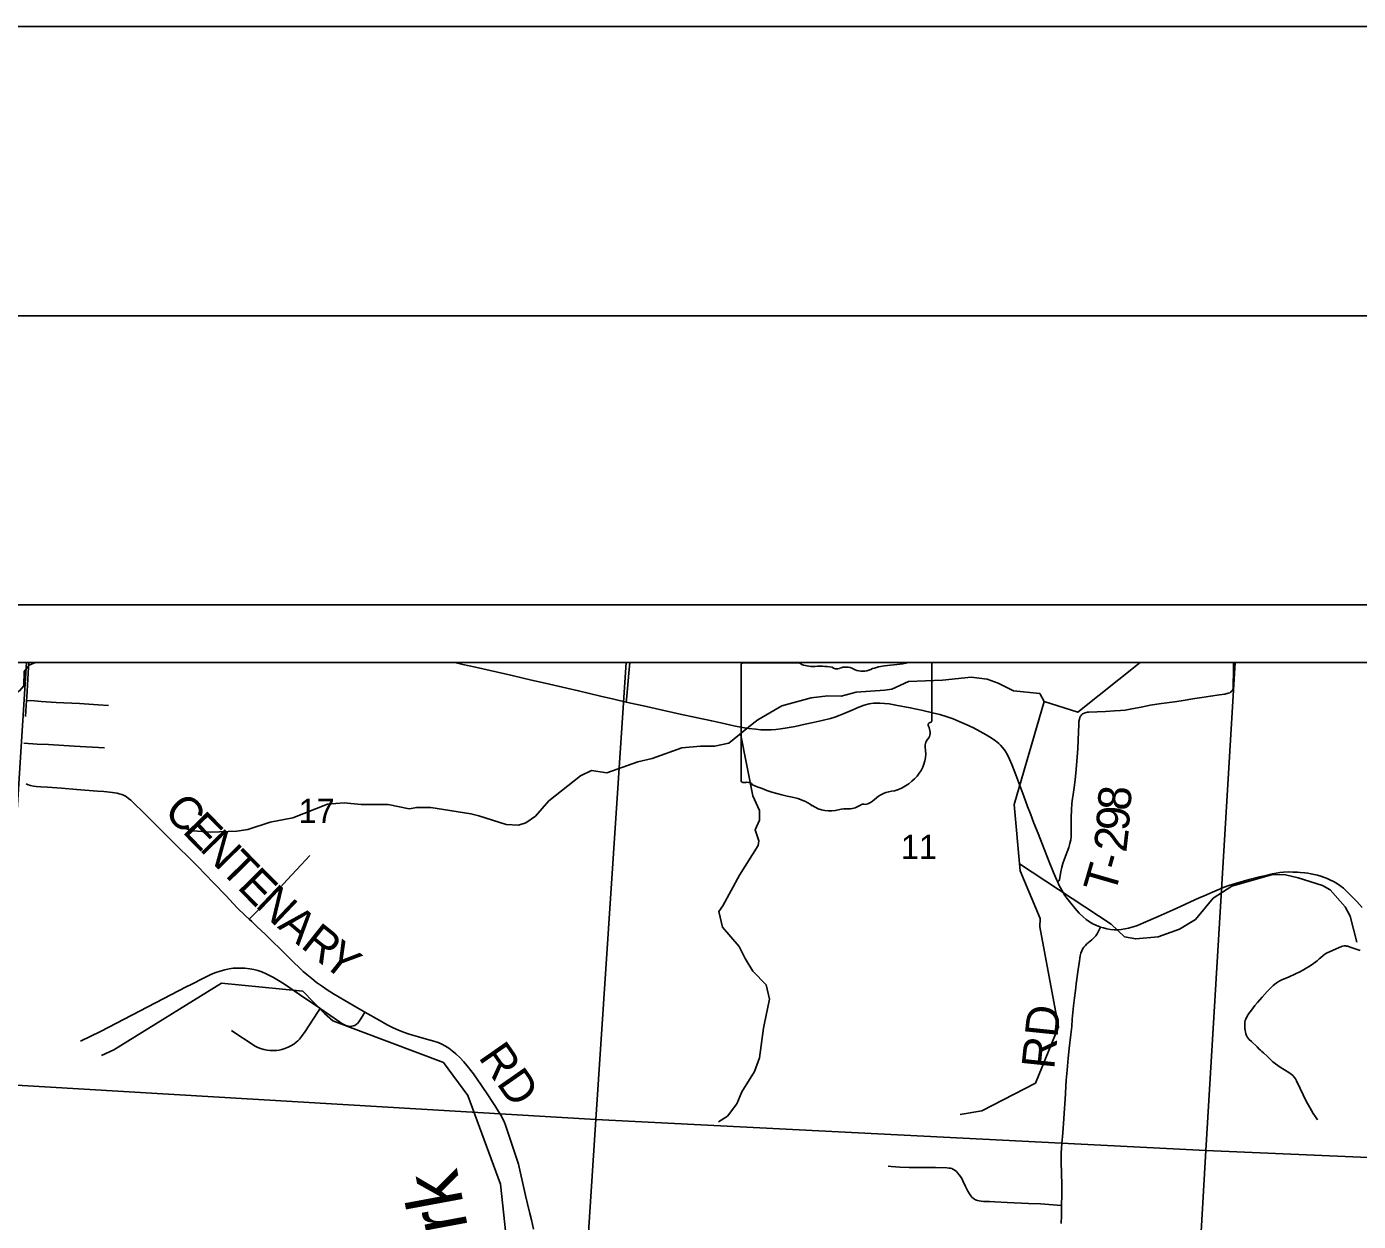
# Model space of a CAD drawing. Extents: x 0 to 34, y 0 to 22.
# Drawn here: x 24.586 to 26.889, y 19.934 to 22 of the extents above; entities that cross this region are included whole.
import ezdxf

# ---------------------------------------------------------------- set-up
doc = ezdxf.new("R2010")
doc.units = 0
for name, color, linetype in [('Default', 7, 'Continuous'), ('GM_X_County_Road', 7, 'Continuous'), ('GM_X_County_Road_Text', 7, 'Continuous'), ('GM_X_Minor_River', 7, 'Continuous'), ('GM_X_Minor_River_Text', 7, 'Continuous'), ('GM_X_Section', 7, 'Continuous'), ('GM_X_Section_Text', 7, 'Continuous'), ('GM_X_State_Location', 7, 'Continuous'), ('GM_X_State_Route', 7, 'Continuous'), ('GM_X_Township_Road', 7, 'Continuous'), ('GM_X_Township_Road_Text', 7, 'Continuous'), ('SH_Border', 7, 'Continuous'), ('SH_Cut_Line', 7, 'Continuous'), ('SH_Data', 7, 'Continuous'), ('SH_Text', 7, 'Continuous')]:
    doc.layers.add(name, color=color, linetype=linetype)

msp = doc.modelspace()

# ---------------------------------------------------------------- linework, layer by layer
at = {"layer": 'Default'}
for p, q in [((25.8216, 20.8963), (25.8216, 20.6962)), ((25.9214, 20.8998), (25.8248, 20.8998))]:
    msp.add_line(p, q, dxfattribs=at)
for points in [[(27.7198, 20.9), (23.5167, 20.9), (23.5167, 16.1239), (23.5888, 16.1195), (25.0535, 16.0331), (25.3458, 16.0191), (26.0811, 15.9921), (26.3691, 15.9829), (26.8773, 15.953), (26.8866, 15.9536), (26.8953, 15.9537)], [(26.1511, 20.8001), (26.1511, 20.8001), (26.1512, 20.8), (26.1512, 20.9), (26.1115, 20.9)]]:
    msp.add_lwpolyline(points, dxfattribs=at)
for points in [[(25.6226, 20.9), (24.5856, 20.9), (24.5388, 20.1708), (25.5703, 20.1097)], [(26.6756, 20.9), (25.6226, 20.9), (25.5703, 20.1097), (26.6253, 20.056)], [(27.7187, 20.9), (26.6756, 20.9), (26.6253, 20.056), (27.6689, 20.0112)]]:
    msp.add_lwpolyline(points, close=True, dxfattribs=at)
for centre, major_axis, start_param, end_param in [((25.8254, 20.8968), (0.00382, 0), 1.727492, 3.291633), ((25.9443, 20.923), (0.037, 0), 4.042888, 4.731792), ((25.9566, 20.7874), (0.133, 0), 1.404758, 1.657859), ((25.9868, 20.8978), (0.0107, 0), 3.836095, 5.185415), ((26.0025, 20.8747), (0.0222, 0), 0.950623, 2.079405), ((26.0783, 20.8386), (0.0703, 0), 1.699012, 2.107814), ((26.0338, 21.1726), (0.3495, 0), 4.814394, 4.936803), ((26.0312, 20.9064), (0.0267, 0), 4.08156, 5.145723), ((26.1473, 20.7996), (0.00393, 0), 5.05454, 6.418171), ((26.1503, 20.7924), (0.00568, 0), 1.883978, 3.671073), ((26.1142, 20.7791), (0.0341, 0), 5.934695, 6.695948), ((26.0533, 20.7429), (0.0874, 0), 5.101753, 6.440018), ((26.1643, 20.7562), (0.0248, 0), 2.387724, 3.262537), ((25.8254, 20.6958), (0.00385, 0), 2.993084, 4.5083), ((25.826, 20.7162), (0.0294, 0), 4.665946, 4.897461), ((25.832, 20.6847), (0.0106, 0), 0.519207, 1.627899), ((25.9658, 20.8645), (0.2524, 0), 4.195997, 4.488961), ((25.8906, 20.6063), (0.079, 0), 0.823519, 1.323587), ((26.0295, 20.6768), (0.0282, 0), 4.937069, 5.64225), ((26.0902, 20.64), (0.0479, 0), 1.647645, 2.488434), ((25.976, 20.6837), (0.0501, 0), 4.026481, 4.996735), ((26.0049, 20.6145), (0.0412, 0), 1.495662, 1.94098), ((26.0086, 20.6687), (0.0267, 0), 4.691044, 5.507374), ((26.0327, 20.6493), (0.00752, 0), 1.147584, 2.315152)]:
    msp.add_ellipse(centre, major_axis=major_axis, ratio=0.8, start_param=start_param, end_param=end_param, dxfattribs=at)
at = {"layer": 'GM_X_County_Road'}
for points in [[(24.5838, 20.8068), (24.5857, 20.8348), (24.586, 20.8406), (24.5871, 20.8611), (24.5885, 20.8822), (24.5897, 20.8995), (24.5897, 20.9)], [(25.4623, 19.9205), (25.4588, 19.9363), (25.4562, 19.9472), (25.4522, 19.9641), (25.4487, 19.9786), (25.4464, 19.9889), (25.444, 19.9992), (25.4398, 20.0173), (25.4361, 20.0324), (25.4335, 20.0414), (25.4284, 20.0567), (25.4217, 20.0761), (25.4143, 20.0986), (25.4114, 20.1067), (25.4088, 20.1118), (25.4068, 20.1156), (25.402, 20.1237), (25.3953, 20.1342), (25.3894, 20.1429), (25.3842, 20.1507), (25.3721, 20.1687), (25.3583, 20.1886), (25.3539, 20.1947), (25.3478, 20.2025), (25.3413, 20.2101), (25.3352, 20.2164), (25.3281, 20.2233), (25.3219, 20.2287), (25.3159, 20.2332), (25.3101, 20.2369), (25.304, 20.2401), (25.2976, 20.2428), (25.2899, 20.2454), (25.2774, 20.2491), (25.2636, 20.2529), (25.2475, 20.2575), (25.2375, 20.2608), (25.2289, 20.2642), (25.2198, 20.2682), (25.2094, 20.2736), (25.1953, 20.2815), (25.1708, 20.2956), (25.1679, 20.2973), (25.1565, 20.3037), (25.1362, 20.3157), (25.1165, 20.3275), (25.1054, 20.3344), (25.0972, 20.3399), (25.0871, 20.3471), (25.0788, 20.3535), (25.0703, 20.3606), (25.0642, 20.3659), (25.0592, 20.3705), (25.0453, 20.3838), (25.0344, 20.3948), (25.0278, 20.4014), (25.0074, 20.4214), (24.998, 20.4305), (24.9844, 20.4433), (24.9749, 20.4521), (24.9703, 20.4562), (24.9634, 20.4625), (24.9499, 20.4762), (24.93, 20.4971), (24.9093, 20.5189), (24.8941, 20.5345), (24.8828, 20.5461), (24.8697, 20.5593), (24.845, 20.5838), (24.834, 20.5948), (24.8171, 20.6112), (24.8078, 20.6204), (24.7913, 20.6372), (24.7839, 20.6447), (24.7754, 20.653), (24.7659, 20.6619), (24.7621, 20.6653), (24.7581, 20.6683), (24.7558, 20.6695), (24.7532, 20.6707), (24.7506, 20.6718), (24.746, 20.6733), (24.7421, 20.6742), (24.7341, 20.6755), (24.7192, 20.677), (24.708, 20.678), (24.6721, 20.6807), (24.6461, 20.6827), (24.6219, 20.6846), (24.6101, 20.6853), (24.6021, 20.686), (24.5978, 20.6865), (24.5924, 20.6875), (24.5883, 20.6887), (24.5862, 20.6897), (24.5846, 20.6906)]]:
    msp.add_lwpolyline(points, dxfattribs=at)
at = {"layer": 'GM_X_Minor_River'}
for points in [[(24.6012, 20.9), (24.5899, 20.8956), (24.5812, 20.8846), (24.5808, 20.8599), (24.5732, 20.8511), (24.5626, 20.845), (24.5535, 20.831), (24.5372, 20.8089), (24.5118, 20.7921), (24.486, 20.7666), (24.4792, 20.7628), (24.4651, 20.7282), (24.4211, 20.6669), (24.3878, 20.6262), (24.3703, 20.595), (24.3574, 20.581), (24.3517, 20.5745), (24.3286, 20.5539), (24.3187, 20.5383)], [(26.5115, 20.9), (26.4036, 20.8143), (26.3457, 20.8331), (26.2934, 20.6546), (26.304, 20.5397), (26.3388, 20.4577), (26.3379, 20.4433), (26.3705, 20.2701), (26.3304, 20.1726), (26.2377, 20.1247), (26.2002, 20.1187)], [(26.3456, 20.8331), (26.3378, 20.8465), (26.2927, 20.851), (26.2661, 20.8647), (26.2468, 20.8715), (26.2191, 20.8749), (26.1695, 20.8699), (26.1111, 20.8676), (26.0819, 20.8539), (26.0698, 20.8527), (26.0201, 20.8492), (25.9947, 20.842), (25.9712, 20.8427), (25.9424, 20.8389), (25.892, 20.8251), (25.8503, 20.8011), (25.8431, 20.7962), (25.8002, 20.7608), (25.7756, 20.7554), (25.7513, 20.7554), (25.7191, 20.7527), (25.6675, 20.734), (25.6425, 20.7283), (25.5894, 20.7092), (25.5625, 20.7134), (25.5436, 20.7043), (25.4886, 20.6608), (25.4655, 20.6346), (25.4488, 20.6228), (25.4366, 20.619), (25.415, 20.6201), (25.3677, 20.6352), (25.354, 20.6387), (25.2846, 20.6496), (25.2604, 20.6496), (25.2471, 20.6473), (25.2107, 20.6545), (25.1641, 20.6548), (25.1349, 20.6578), (25.1061, 20.6551), (25.0462, 20.6315), (25.0068, 20.6242), (24.9681, 20.6116), (24.9495, 20.6086), (24.9044, 20.607), (24.8737, 20.6093), (24.8574, 20.6138)], [(25.8205, 20.7775), (25.8415, 20.6696), (25.8533, 20.6441), (25.8529, 20.6274), (25.8457, 20.6107), (25.8521, 20.5917), (25.851, 20.584), (25.8187, 20.5327), (25.7899, 20.4794), (25.7831, 20.4695), (25.7891, 20.4426), (25.8179, 20.4091), (25.8281, 20.3882), (25.8418, 20.3662), (25.8645, 20.343), (25.8706, 20.3179), (25.8611, 20.2734), (25.8603, 20.2681), (25.8531, 20.2168), (25.8444, 20.1928), (25.8224, 20.1575), (25.814, 20.1369), (25.7977, 20.1156), (25.7822, 20.1061)], [(26.3029, 20.5519), (26.4612, 20.4475), (26.4846, 20.4257), (26.504, 20.4221), (26.5426, 20.4256), (26.5793, 20.4393), (26.6075, 20.456), (26.6378, 20.4928), (26.6699, 20.5133), (26.7402, 20.5335), (26.7626, 20.533), (26.785, 20.5276), (26.8269, 20.5147), (26.8402, 20.5069), (26.8663, 20.4779), (26.8745, 20.4616), (26.886, 20.4165)], [(25.6073, 18.8574), (25.5886, 18.9702), (25.6029, 19.0352), (25.6012, 19.1623), (25.5582, 19.2276), (25.4917, 19.2911), (25.4923, 19.3594), (25.4708, 19.4097), (25.4737, 19.5938), (25.4713, 19.6579), (25.427, 19.7941), (25.4053, 19.9981), (25.349, 20.1513), (25.3065, 20.2086), (25.115, 20.2805), (25.1008, 20.2933), (25.0631, 20.3317), (24.9228, 20.3456), (24.7364, 20.2301), (24.7153, 20.2204)]]:
    msp.add_lwpolyline(points, dxfattribs=at)
at = {"layer": 'GM_X_Section'}
for points in [[(24.5388, 20.1708), (25.5703, 20.1097), (25.5433, 19.6923), (25.5164, 19.2759), (25.5041, 19.0909), (25.5038, 19.0874), (24.9075, 19.1174), (24.4668, 19.1382), (24.4804, 19.3317), (24.5096, 19.7459)], [(25.5703, 20.1097), (26.6253, 20.056), (26.6008, 19.6356), (25.5433, 19.6923)], [(27.6689, 20.0112), (27.6061, 18.9865), (26.5652, 19.0298), (26.5757, 19.2125), (26.6008, 19.6356), (26.6253, 20.056)]]:
    msp.add_lwpolyline(points, close=True, dxfattribs=at)
at = {"layer": 'GM_X_State_Route'}
for points in [[(25.3264, 20.9), (25.34, 20.8969), (25.3619, 20.8923), (25.4254, 20.8778), (25.4586, 20.8699), (25.4823, 20.8646), (25.5198, 20.8561), (25.5404, 20.8513), (25.5784, 20.842), (25.6014, 20.8368), (25.6228, 20.8318)], [(25.6228, 20.8318), (25.6578, 20.8239), (25.6729, 20.8206), (25.716, 20.8111), (25.7433, 20.8054), (25.7705, 20.7993), (25.7863, 20.7959), (25.8088, 20.791), (25.824, 20.788), (25.8345, 20.7863), (25.8469, 20.7847), (25.8556, 20.784), (25.8643, 20.7837), (25.8731, 20.7838), (25.8812, 20.7844), (25.8899, 20.7853), (25.9009, 20.7871), (25.915, 20.7898), (25.932, 20.7936), (25.946, 20.7966), (25.9617, 20.8001), (25.9757, 20.8035), (25.9834, 20.8058), (25.9911, 20.8085), (25.9998, 20.8119), (26.0146, 20.8184), (26.0249, 20.8228), (26.0341, 20.8262), (26.043, 20.8285), (26.0503, 20.8297), (26.054, 20.83), (26.0579, 20.8301), (26.0613, 20.8301), (26.0693, 20.8295), (26.0773, 20.8285), (26.0889, 20.8266), (26.1139, 20.8219), (26.1358, 20.8174), (26.1521, 20.8135), (26.1653, 20.8101), (26.1778, 20.8063), (26.1883, 20.8026), (26.1986, 20.7985), (26.2105, 20.7933), (26.2234, 20.7871), (26.2349, 20.7811), (26.2452, 20.7754), (26.2541, 20.7698), (26.2612, 20.7649), (26.2669, 20.7602), (26.27, 20.7572), (26.2737, 20.7532), (26.2759, 20.7505), (26.278, 20.7473), (26.2821, 20.7404), (26.2856, 20.7332), (26.2893, 20.724), (26.2963, 20.7061), (26.3053, 20.6829), (26.3106, 20.669), (26.3169, 20.6515), (26.3216, 20.6386), (26.3279, 20.6224), (26.335, 20.6046), (26.3421, 20.5867), (26.3542, 20.5554), (26.3615, 20.5369), (26.3668, 20.5249), (26.3684, 20.5215), (26.3717, 20.5148), (26.3761, 20.5065), (26.3815, 20.4974), (26.3846, 20.4927), (26.3915, 20.4838), (26.3991, 20.4747), (26.4063, 20.4669), (26.4129, 20.4603), (26.4182, 20.4558), (26.4239, 20.4519), (26.4299, 20.4485), (26.4361, 20.4456), (26.4396, 20.4441), (26.4432, 20.4428), (26.4479, 20.4412), (26.454, 20.4397), (26.4602, 20.4387), (26.4665, 20.4382), (26.4721, 20.4382), (26.4784, 20.4386), (26.4852, 20.4395), (26.4914, 20.4408), (26.4992, 20.443), (26.5069, 20.4456), (26.5173, 20.4498), (26.5424, 20.4608), (26.5684, 20.4727), (26.5887, 20.482), (26.5983, 20.4864), (26.6124, 20.4926), (26.622, 20.4967), (26.6314, 20.5007), (26.6365, 20.5031), (26.6449, 20.5067), (26.6514, 20.5093), (26.6568, 20.5115), (26.665, 20.5144), (26.6762, 20.5179), (26.7001, 20.5247), (26.7181, 20.5294), (26.7296, 20.5321), (26.7405, 20.5345), (26.7533, 20.5368), (26.7596, 20.5376), (26.768, 20.538), (26.7754, 20.5379), (26.7834, 20.5377), (26.7885, 20.5373), (26.7962, 20.5366), (26.8014, 20.5358), (26.8068, 20.5349), (26.8122, 20.5338), (26.8182, 20.5323), (26.8241, 20.5306), (26.8285, 20.5291), (26.8321, 20.5277), (26.8352, 20.5265), (26.8398, 20.5246), (26.8458, 20.5217), (26.8511, 20.5185), (26.8567, 20.5147), (26.863, 20.5097), (26.8691, 20.5045), (26.8744, 20.4993), (26.8863, 20.4867), (26.8956, 20.4767)]]:
    msp.add_lwpolyline(points, dxfattribs=at)
at = {"layer": 'GM_X_Township_Road'}
for points in [[(25.6228, 20.8318), (25.6233, 20.8367), (25.6239, 20.8422), (25.6274, 20.8818), (25.6291, 20.9)], [(26.4057, 20.7983), (26.4064, 20.802), (26.4073, 20.805), (26.4084, 20.8073), (26.4093, 20.8088), (26.4103, 20.8099), (26.4118, 20.8113), (26.4133, 20.8123), (26.4163, 20.8135), (26.4181, 20.814), (26.4204, 20.8144), (26.4226, 20.8146), (26.437, 20.8152), (26.4518, 20.8158), (26.4673, 20.8164), (26.4777, 20.8171), (26.4857, 20.818), (26.4943, 20.8194), (26.5162, 20.8237), (26.529, 20.8262), (26.5487, 20.8293), (26.5708, 20.8322), (26.5825, 20.834), (26.6063, 20.8382), (26.618, 20.8399), (26.6334, 20.842), (26.6488, 20.8441), (26.6579, 20.8456), (26.6638, 20.8472), (26.6664, 20.8481), (26.668, 20.8491), (26.67, 20.8509), (26.671, 20.8523), (26.6717, 20.8537), (26.6721, 20.8554), (26.6722, 20.8571), (26.6726, 20.8632), (26.6727, 20.8824), (26.6732, 20.8972), (26.6733, 20.9)], [(24.5857, 20.8348), (24.599, 20.8337), (24.6107, 20.8328), (24.6367, 20.8312), (24.677, 20.8291), (24.7094, 20.8271), (24.7272, 20.8261)], [(26.3946, 20.6658), (26.3948, 20.6677), (26.3971, 20.6843), (26.3989, 20.6972), (26.4008, 20.7151), (26.4027, 20.7368), (26.4036, 20.7516), (26.4048, 20.7802), (26.4052, 20.7926), (26.4057, 20.7983)], [(24.5806, 20.7609), (24.6039, 20.7593), (24.6237, 20.7583), (24.6678, 20.7556), (24.7203, 20.7527)], [(26.3684, 20.5215), (26.3706, 20.5224), (26.3718, 20.5242), (26.3728, 20.5286), (26.3745, 20.5383), (26.3762, 20.5462), (26.378, 20.5528), (26.3805, 20.5605), (26.3879, 20.5803), (26.3901, 20.5873), (26.3915, 20.5933), (26.3921, 20.5995), (26.3923, 20.6075), (26.3923, 20.6324), (26.3927, 20.6454), (26.3935, 20.656), (26.3946, 20.6658)], [(24.9703, 20.4562), (24.9744, 20.4603), (24.9906, 20.4765), (25.0062, 20.4925), (25.0245, 20.5118), (25.0364, 20.5244), (25.0604, 20.5503), (25.0756, 20.5664)], [(26.3751, 19.9302), (26.3754, 19.9438), (26.3756, 19.9613), (26.3758, 19.9798), (26.3758, 19.9972), (26.3755, 20.0165), (26.375, 20.0364), (26.3751, 20.0519), (26.3754, 20.0606), (26.3758, 20.0681), (26.3775, 20.0866), (26.3798, 20.1114), (26.3809, 20.1287), (26.3816, 20.1442), (26.3833, 20.1779), (26.385, 20.1953), (26.3872, 20.216), (26.389, 20.2327), (26.3917, 20.2568), (26.3931, 20.271), (26.3942, 20.2834), (26.3964, 20.3062), (26.398, 20.3204), (26.3995, 20.3328), (26.401, 20.3445), (26.4045, 20.3691), (26.4058, 20.3802), (26.408, 20.3931), (26.409, 20.3974), (26.4105, 20.4015), (26.4125, 20.4055), (26.4142, 20.4081), (26.4167, 20.411), (26.4194, 20.4136), (26.4281, 20.4206), (26.4321, 20.4244), (26.4348, 20.4277), (26.437, 20.4311), (26.4392, 20.4354), (26.4432, 20.4428)], [(26.8182, 20.1091), (26.8145, 20.1146), (26.8108, 20.1204), (26.8047, 20.1309), (26.7988, 20.1417), (26.7932, 20.1523), (26.788, 20.1634), (26.782, 20.177), (26.7802, 20.1803), (26.7784, 20.1828), (26.7754, 20.186), (26.7726, 20.1884), (26.7686, 20.1912), (26.7538, 20.2005), (26.7494, 20.2035), (26.7456, 20.2061), (26.7412, 20.2096), (26.7367, 20.2137), (26.7315, 20.2187), (26.7248, 20.2251), (26.722, 20.2276), (26.7197, 20.2297), (26.7175, 20.2318), (26.714, 20.2353), (26.704, 20.2446), (26.7, 20.2485), (26.6972, 20.2519), (26.6959, 20.254), (26.695, 20.2561), (26.6942, 20.2583), (26.6935, 20.2618), (26.6932, 20.2641), (26.6928, 20.2676), (26.6926, 20.2714), (26.6925, 20.2749), (26.6928, 20.2782), (26.6934, 20.2813), (26.6942, 20.2837), (26.6966, 20.2886), (26.6995, 20.2932), (26.7038, 20.2991), (26.71, 20.3068), (26.7142, 20.312), (26.7224, 20.3213), (26.7311, 20.331), (26.7375, 20.3378), (26.7416, 20.3416), (26.747, 20.3458), (26.7522, 20.3491), (26.7578, 20.3519), (26.768, 20.3563), (26.78, 20.3616), (26.7878, 20.3653), (26.7938, 20.3686), (26.7989, 20.3714), (26.8029, 20.374), (26.809, 20.3782), (26.8174, 20.3845), (26.8214, 20.3876), (26.8237, 20.3895), (26.8278, 20.3933), (26.831, 20.3958), (26.8339, 20.3975), (26.8456, 20.4028), (26.8546, 20.4069), (26.8596, 20.409), (26.8619, 20.4097), (26.8643, 20.41), (26.8664, 20.4101), (26.8684, 20.4098), (26.8709, 20.4094), (26.8745, 20.4082), (26.8815, 20.4056), (26.8866, 20.4037), (26.8919, 20.4023)], [(24.679, 20.2452), (24.7132, 20.2621), (24.8629, 20.3397), (24.8689, 20.3428), (24.8927, 20.3548), (24.9056, 20.361), (24.913, 20.3641), (24.9205, 20.3667), (24.9283, 20.3688), (24.9361, 20.3704), (24.9428, 20.3714), (24.9483, 20.3718), (24.9517, 20.3719), (24.9551, 20.3719), (24.9631, 20.3714), (24.9717, 20.3704), (24.9789, 20.3691), (24.9854, 20.3674), (24.9924, 20.365), (24.9999, 20.362), (25.006, 20.3591), (25.0125, 20.3555), (25.0215, 20.3501), (25.0314, 20.3437), (25.0576, 20.3259), (25.0926, 20.3023), (25.0933, 20.3018), (25.127, 20.2789), (25.1322, 20.2755), (25.1367, 20.2731), (25.1397, 20.2719), (25.1422, 20.2713), (25.1455, 20.271), (25.1481, 20.2712), (25.1507, 20.2718), (25.1531, 20.2727), (25.1559, 20.2745), (25.1578, 20.2762), (25.16, 20.2786), (25.1625, 20.2822), (25.1665, 20.2886), (25.1708, 20.2956)], [(24.9398, 20.2641), (24.9546, 20.2542), (24.9651, 20.247), (24.9729, 20.2419), (24.9808, 20.237), (24.9853, 20.2346), (24.99, 20.2327), (24.996, 20.2308), (25.0015, 20.2297), (25.0065, 20.2291), (25.0122, 20.229), (25.0179, 20.2293), (25.0222, 20.23), (25.0271, 20.231), (25.0325, 20.2327), (25.0378, 20.2348), (25.0429, 20.2373), (25.0477, 20.2403), (25.0517, 20.2434), (25.0545, 20.2459), (25.0575, 20.2491), (25.0611, 20.2535), (25.0672, 20.2622), (25.0887, 20.2948), (25.0933, 20.3018)], [(26.0757, 20.0293), (26.0808, 20.0287), (26.0881, 20.0281), (26.0956, 20.0277), (26.1121, 20.0271), (26.1464, 20.0267), (26.1574, 20.0267), (26.1772, 20.0265), (26.1814, 20.026), (26.1837, 20.0255), (26.1859, 20.0249), (26.1875, 20.0241), (26.1889, 20.0234), (26.1915, 20.0219), (26.1938, 20.02), (26.1959, 20.0178), (26.1986, 20.0144), (26.2008, 20.0111), (26.2029, 20.0077), (26.2049, 20.0039), (26.2091, 19.995), (26.2135, 19.986), (26.2164, 19.9811), (26.2185, 19.978), (26.2206, 19.9756), (26.2234, 19.9731), (26.225, 19.9721), (26.2267, 19.9711), (26.2284, 19.9704), (26.2302, 19.9697), (26.2333, 19.969), (26.2363, 19.9685), (26.2407, 19.9682), (26.2507, 19.9679), (26.26, 19.9675), (26.2817, 19.9665), (26.3182, 19.9649), (26.3393, 19.9639), (26.3756, 19.9613)]]:
    msp.add_lwpolyline(points, dxfattribs=at)
at = {"layer": 'SH_Border'}
msp.add_lwpolyline([(1.5, 21.5), (33.5, 21.5), (33.5, 0.5), (1.5, 0.5)], close=True, dxfattribs=at)
at = {"layer": 'SH_Cut_Line'}
msp.add_lwpolyline([(0, 0), (34, 0), (34, 22), (0, 22)], close=True, dxfattribs=at)
at = {"layer": 'SH_Data'}
for points in [[(23.4167, 21), (30.4167, 21), (30.4167, 14), (23.4167, 14)], [(23.5167, 20.9), (30.3167, 20.9), (30.3167, 14.1), (23.5167, 14.1)]]:
    msp.add_lwpolyline(points, close=True, dxfattribs=at)
at = {"layer": 'SH_Text'}
msp.add_lwpolyline([(30.3167, 20.9), (23.5167, 20.9), (23.5167, 14.1), (29.5051, 14.1)], dxfattribs=at)

# ---------------------------------------------------------------- texts
at = {"layer": 'GM_X_County_Road_Text'}
for s, height, rotation, p in [('C', 0.0568, 314.3928, (24.8208, 20.6405)), ('E', 0.0568, 314.3922, (24.8534, 20.6072)), ('N', 0.0568, 314.3921, (24.8832, 20.5768)), ('T', 0.0568, 314.4094, (24.9182, 20.5411)), ('E', 0.0568, 314.8988, (24.9483, 20.5104)), ('N', 0.0568, 316.4436, (24.9795, 20.4791)), ('A', 0.0568, 319.5218, (25.0182, 20.4424)), ('R', 0.0568, 321.4007, (25.0578, 20.4086)), ('Y', 0.0568, 321.4851, (25.0943, 20.3795)), ('RD', 0.05682, 304.9108, (25.3658, 20.2175))]:
    msp.add_text(s, height=height, rotation=rotation, dxfattribs=at).set_placement(p)
at = {"layer": 'GM_X_Minor_River_Text'}
msp.add_text('Fork', height=0.09468, rotation=100.5169, dxfattribs=at).set_placement((25.376, 19.7774))
at = {"layer": 'GM_X_Section_Text'}
for s, p in [('17', (25.0562, 20.6228)), ('11', (26.0979, 20.5606))]:
    msp.add_text(s, height=0.04186, rotation=0, dxfattribs=at).set_placement(p)
at = {"layer": 'GM_X_State_Location'}
for s in ['s', 'r']:
    msp.add_text(s, height=0.000189, dxfattribs=at).set_placement((25.9827, 20.783))
msp.add_text('588', height=0.000189, rotation=0, dxfattribs=at).set_placement((25.9158, 20.7692))
at = {"layer": 'GM_X_Township_Road_Text'}
for s, height, rotation, p in [('8', 0.0568, 85.6504, (26.4942, 20.6428)), ('9', 0.0568, 85.7618, (26.4916, 20.6079)), ('2', 0.0568, 83.4454, (26.4874, 20.5706)), ('T', 0.0568, 73.7773, (26.4672, 20.4971)), ('-', 0.0568, 74.3163, (26.4792, 20.5385)), ('RD', 0.05682, 84.0946, (26.3627, 20.1957))]:
    msp.add_text(s, height=height, rotation=rotation, dxfattribs=at).set_placement(p)

doc.saveas('drawing.dxf')
